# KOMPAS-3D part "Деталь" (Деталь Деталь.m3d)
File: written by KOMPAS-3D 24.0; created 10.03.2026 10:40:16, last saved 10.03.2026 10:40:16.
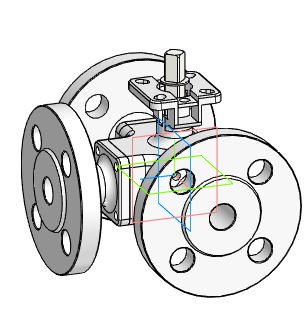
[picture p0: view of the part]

Document properties: Автор: R2D2; Полное имя файла: C:\Users\R2D2\Downloads\Деталь Деталь.m3d

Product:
- Body: Твердое тело1  | qty 1
- Part/product: Деталь
    additional columns: Типовые

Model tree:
1. Твердое тело1  (labels: Твердое тело1)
